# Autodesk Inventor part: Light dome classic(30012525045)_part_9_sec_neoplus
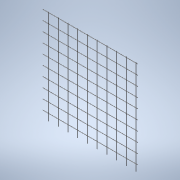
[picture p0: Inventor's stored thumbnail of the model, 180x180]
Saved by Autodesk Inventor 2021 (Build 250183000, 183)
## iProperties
Created: 2026-04
Part Number: Light dome classic(30012525045)_part_9_sec_neoplus
Material: Generic
Catalog Web Link: www.3dfindit.com
Description: Light dome classic_part_9_sec_neoplus-
Vendor: KINGSPAN
Document SubType Name: Modeling
Designer: psAdmin
Manufacturer: KINGSPAN
Mass: 383.088 g
Surface Area: 3074.65 cm^2
Volume: 383.088 cm^3
Density: 1 g/cm^3
Appearance: PSOLRGB-255-255-255
Category: PARTsolutions
Company: KINGSPAN
Title: Light dome classic(30012525045)_part_9_sec_neoplus
Author: Cadenas PARTsolutions
PSOL_IDENT_0: {$CADENAS_DATA/23d-libs/kingspan_kla/light_dome_classic_neoplus/parts/part_9_sec.prj},290 {VTYP=3D},
PSOL_IDENT_1: {NB=Light dome classic(30012525045)_part_9_sec_neoplus},{LINA=Light dome classic(30012525045)_part_9
PSOL_IDENT_2: _sec_neoplus},{NN=Light dome classic_part_9_sec_neoplus},{DATE=15.07.2024 10:56:16},{GEOMDATE=28.06.
PSOL_IDENT_3: 2024 11:51:14},{VERSION=},{LINEID=10},{WBVAR=LODLEVEL,L,W,DP,OP},{WBNUMERIC=W}  {NB=Light dome class
PSOL_IDENT_4: ic(30012525045)_part_9_sec_neoplus},{LINA=Light dome classic(30012525045)_part_9_sec_neoplus},{KT=DU
PSOL_IDENT_5: MMY},{IDNR=},{PN=Light dome classic},{LODLEVEL=300},{L=125},{W=250},{WX=125,250,300},{LX=1250},{XWX=
PSOL_IDENT_6: 2500},{DP=4},{OPX='5','Pneumatic - NRWG F.6 LK'},{OP=5},{DRIVE=1},{DPX='1', 'Natural ventilation', '
PSOL_IDENT_7: 2' , 'NSHEV (natural smoke, heat exhaust ventilation)', '3', 'Fixed','4','NSHE'}
NB: Light dome classic(30012525045)_part_9_sec_neoplus
NN: Light dome classic_part_9_sec_neoplus
NBSYN: $PN.($LODLEVEL.$L.$W.$DP.$OP.)_part_9_sec_neoplus
LINA: Light dome classic(30012525045)_part_9_sec_neoplus
CATALOG: Light + Air
PN: Light dome classic
LODLEVEL: 300
L: 125
W: 250
DP: NSHE
OP: Pneumatic - NRWG F.6 LK
SUPPLIER: KINGSPAN
ARTICLENO: Light dome classic(30012525045)_part_9_sec_neoplus
BOMINFO: Light dome classic(30012525045)_part_9_sec_neoplus
CREATOR: CADENAS GmbH
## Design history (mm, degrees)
sketch "Sketch_8"
  geometry: C1 r 2.5 at (475, 263.34); 1 further point
  constraints: 1 centre point
extrude "Extrusion1" join sketch "Sketch_8" stored distance "d0" = 2225; taper "d1" = 0 deg
sketch "Sketch_1"
  geometry: C1 r 2.5 at (-1100, 268.32); 1 further point
  constraints: 1 centre point
extrude "Extrusion2" join sketch "Sketch_1" stored distance "d2" = 975; taper "d3" = 0 deg
sketch "Sketch_2"
  geometry: C1 r 2.5 at (375, 263.34); 1 further point
  constraints: 1 centre point
extrude "Extrusion3" join sketch "Sketch_2" stored distance "d10" = 2225; taper "d11" = 0 deg
pattern_linear "Rectangular Pattern2" dims "d14" = 100, "d17" = 0
sketch "Sketch_9"
  geometry: L1 (-10, -278.32)-(10, -278.32); L2 (10, -278.32)-(10, -258.32); L3 (10, -258.32)-(-10, -258.32); L4 (-10, -258.32)-(-10, -278.32)
  constraints: 8 end point
extrude "Extrusion4" cut sketch "Sketch_9" stored distance "d18" = 220; taper "d19" = 0 deg
sketch "Sketch_10"
  geometry: L1 (-500, 522.5)-(-500, -522.5); L2 (-500, -522.5)-(0, -522.5); L3 (0, -522.5)-(0, 522.5); L4 (0, 522.5)-(-500, 522.5)
  constraints: 8 end point
extrude "Extrusion5" cut sketch "Sketch_10" distance "d20" = 2635; taper "d21" = 0 deg
node "IP_9_sec_XY"
node "IP_9_sec_YZ"
node "IP_9_sec_ZX"
node "IP_9_sec_X"
node "IP_9_sec_Y"
node "IP_9_sec_Z"
node "IP_9_sec_Center"
body "Solid1"
pattern_linear "Rectangular Pattern1" dims "d6" = 100, "d9" = 0
